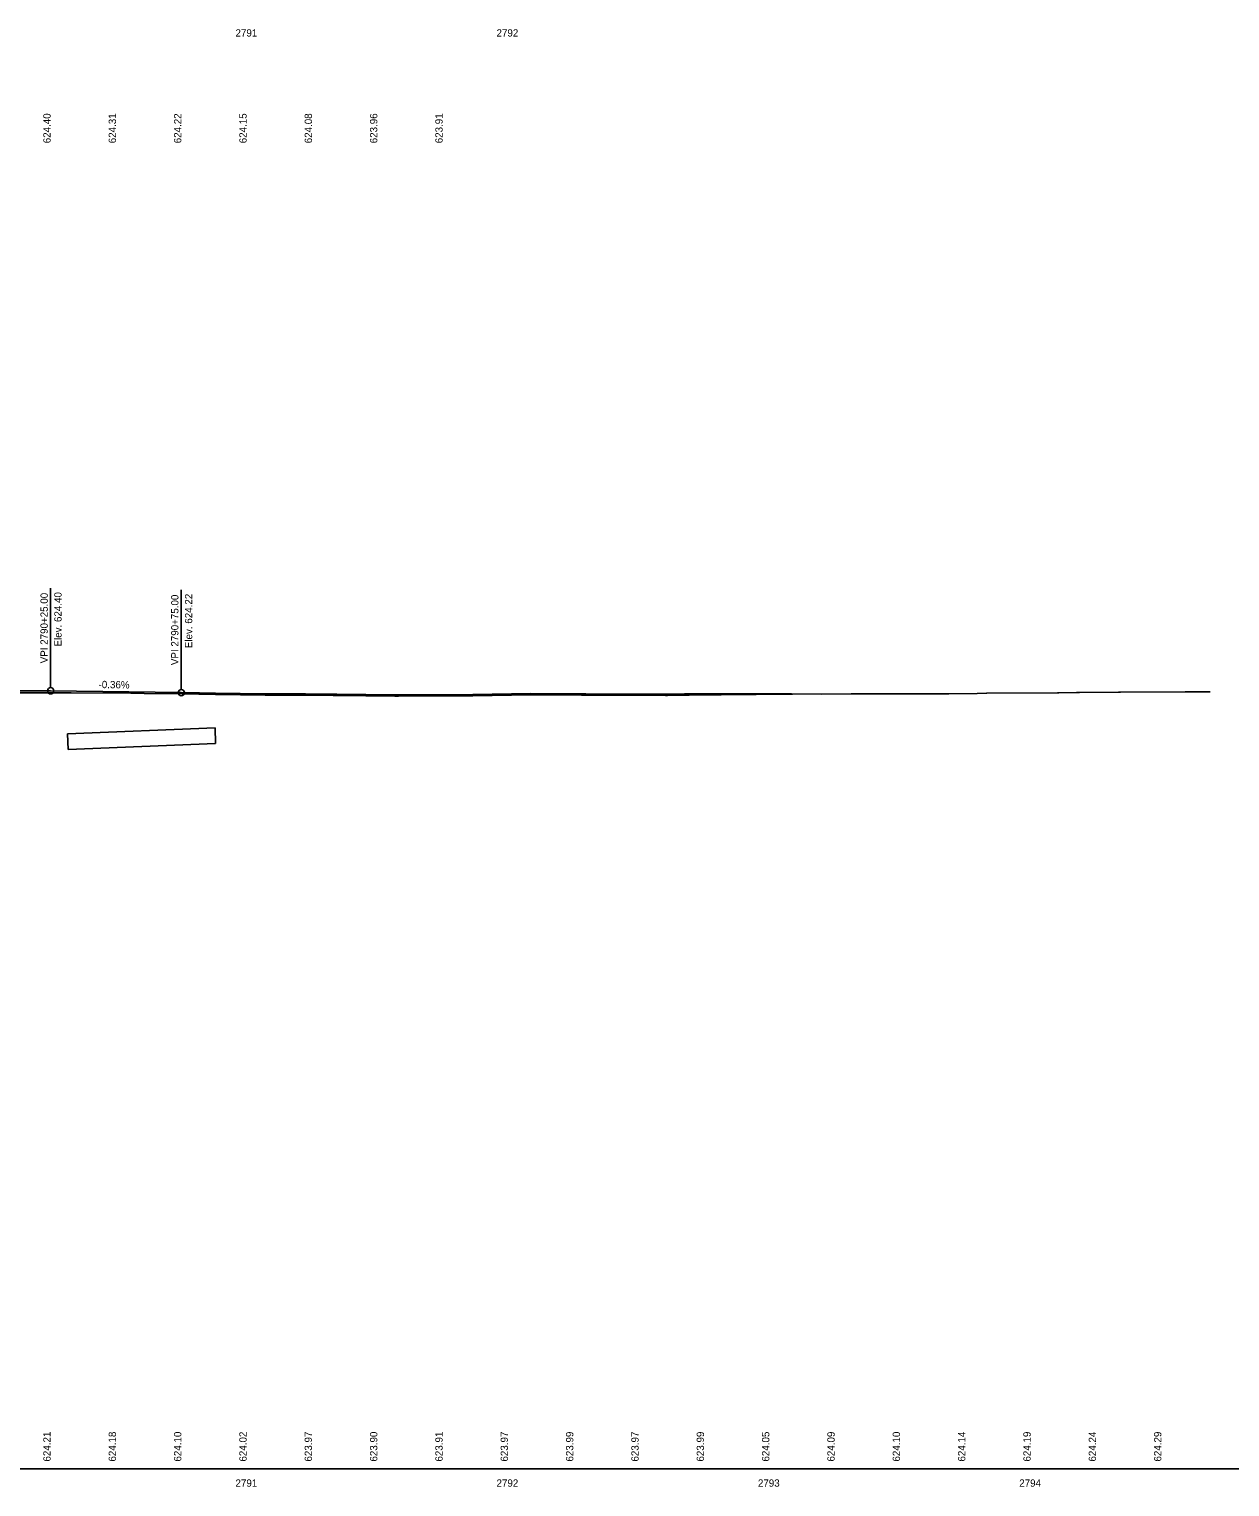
# Model space of a CAD drawing. Extents: x 2376379 to 2383101, y 559608 to 561720.
# Drawn here: x 2379582 to 2380042, y 560612 to 561170 of the extents above; entities that cross this region are included whole.
import ezdxf

# ---------------------------------------------------------------- set-up
doc = ezdxf.new("R2010")
doc.units = 0
for name, color, linetype in [('AP_P_Airside', 7, 'Continuous'), ('BR_X_SV_Shot_Marker', 7, 'Continuous'), ('DR_X_Erosion_Control', 7, 'Continuous'), ('DT_X_Island', 7, 'Continuous'), ('PV_X_Driveway', 7, 'Continuous'), ('SV_X_Text', 7, 'Continuous'), ('UT_X_Overhead_Electric', 7, 'Continuous')]:
    doc.layers.add(name, color=color, linetype=linetype)

msp = doc.modelspace()

# ---------------------------------------------------------------- linework, layer by layer
at = {"layer": 'AP_P_Airside'}
for p, q in [((2379590.62, 560918.13), (2379590.62, 560956.2)), ((2379640.62, 560917.42), (2379640.62, 560955.49))]:
    msp.add_line(p, q, dxfattribs=at)
for centre in [(2379590.62, 560916.92), (2379640.62, 560916.21)]:
    msp.add_circle(centre, 1.21, dxfattribs=at)
at = {"layer": 'DT_X_Island'}
for p, q in [((2379597.07, 560900.43), (2379653.52, 560902.71)), ((2379597.07, 560900.43), (2379597.31, 560894.44)), ((2379653.52, 560902.71), (2379653.76, 560896.72)), ((2379597.31, 560894.44), (2379653.76, 560896.72))]:
    msp.add_line(p, q, dxfattribs=at)
at = {"layer": 'PV_X_Driveway'}
msp.add_lwpolyline([(2379574.48, 560916.16), (2379598.49, 560916.15), (2379621.3, 560916), (2379621.85, 560916.01), (2379626.46, 560915.93), (2379640.83, 560915.71), (2379647.32, 560915.6), (2379647.58, 560915.59), (2379653.68, 560915.53), (2379672.76, 560915.3), (2379673.16, 560915.29), (2379698.79, 560915.13), (2379700.08, 560915.11), (2379722.31, 560914.86), (2379723.77, 560914.86), (2379749.27, 560915), (2379752.13, 560915.04), (2379774.32, 560915.32), (2379775.26, 560915.33), (2379793.8, 560915.27), (2379795.46, 560915.28), (2379825.85, 560915.17), (2379826.68, 560915.17), (2379843.27, 560915.32), (2379846.95, 560915.33), (2379847.18, 560915.33), (2379874.13, 560915.58), (2379874.5, 560915.58), (2379896.91, 560915.73), (2379897.5, 560915.73), (2379907.63, 560915.74), (2379924.19, 560915.7), (2379924.32, 560915.7), (2379934.36, 560915.81), (2379945.2, 560915.93), (2379948.67, 560915.96), (2379948.86, 560915.96), (2379975.92, 560916.15), (2379976.39, 560916.15), (2379983.21, 560916.23), (2379984.36, 560916.23), (2379999.16, 560916.34), (2379999.93, 560916.35), (2380024.78, 560916.54), (2380034.36, 560916.55)], dxfattribs=at)
at = {"layer": 'SV_X_Text'}
msp.add_line((2378765.62, 560619.32), (2380329.61, 560619.32), dxfattribs=at)
at = {"layer": 'UT_X_Overhead_Electric'}
for p, q in [((2379299.62, 560916.92), (2379590.62, 560916.92)), ((2379590.62, 560916.92), (2379640.62, 560916.21))]:
    msp.add_line(p, q, dxfattribs=at)
for points in [[(2379640.62, 560916.21), (2379647.58, 560916.09), (2379653.68, 560916.03), (2379672.76, 560915.8), (2379688.12, 560915.7)], [(2379688.12, 560915.7), (2379698.79, 560915.63), (2379700.08, 560915.61), (2379722.31, 560915.36), (2379723.77, 560915.36), (2379752.13, 560915.54), (2379774.32, 560915.82), (2379795.46, 560915.78), (2379825.85, 560915.67), (2379826.68, 560915.67), (2379833.12, 560915.73)], [(2379833.12, 560915.73), (2379843.27, 560915.72), (2379847.18, 560915.7), (2379874.13, 560915.69), (2379885.62, 560915.65)]]:
    msp.add_lwpolyline(points, dxfattribs=at)

# ---------------------------------------------------------------- texts
at = {"layer": 'AP_P_Airside'}
for s, rotation, p in [('VPI 2790+25.00', 90, (2379589.53, 560927.44)), ('Elev. 624.40', 90, (2379594.82, 560933.86)), ('VPI 2790+75.00', 90, (2379639.53, 560926.74)), ('Elev. 624.22', 90, (2379644.82, 560933.22)), ('-0.36%', 359.1874, (2379608.95, 560917.96))]:
    msp.add_text(s, height=2.8, rotation=rotation, dxfattribs=at).set_placement(p)
at = {"layer": 'BR_X_SV_Shot_Marker'}
for s, p in [('2791', (2379661.36, 561167.19)), ('2792', (2379761.24, 561167.19)), ('2791', (2379661.36, 560612.42)), ('2792', (2379761.24, 560612.42)), ('2793', (2379861.25, 560612.42)), ('2794', (2379961.24, 560612.42))]:
    msp.add_text(s, height=2.8, dxfattribs=at).set_placement(p)
for s, p in [('624.21', (2379590.62, 560622.05)), ('624.18', (2379615.62, 560622.05)), ('624.10', (2379640.62, 560622.05)), ('624.02', (2379665.62, 560622.05)), ('623.97', (2379690.62, 560622.05)), ('623.90', (2379715.62, 560622.05)), ('623.91', (2379740.62, 560622.05)), ('623.97', (2379765.62, 560622.05)), ('623.99', (2379790.62, 560622.05)), ('623.97', (2379815.62, 560622.05)), ('623.99', (2379840.62, 560622.05)), ('624.05', (2379865.62, 560622.05)), ('624.09', (2379890.62, 560622.05)), ('624.10', (2379915.62, 560622.05)), ('624.14', (2379940.62, 560622.05)), ('624.19', (2379965.62, 560622.05)), ('624.24', (2379990.62, 560622.05)), ('624.29', (2380015.62, 560622.05))]:
    msp.add_text(s, height=2.8, rotation=90, dxfattribs=at).set_placement(p)
at = {"layer": 'DR_X_Erosion_Control'}
for s, p in [('624.40', (2379590.62, 561126.37)), ('624.31', (2379615.62, 561126.37)), ('624.22', (2379640.62, 561126.37)), ('624.15', (2379665.62, 561126.37)), ('624.08', (2379690.62, 561126.37)), ('623.96', (2379715.62, 561126.37)), ('623.91', (2379740.62, 561126.37))]:
    msp.add_text(s, height=2.8, rotation=90, dxfattribs=at).set_placement(p)

doc.saveas('drawing.dxf')
